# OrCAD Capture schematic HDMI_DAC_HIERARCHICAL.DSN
size A
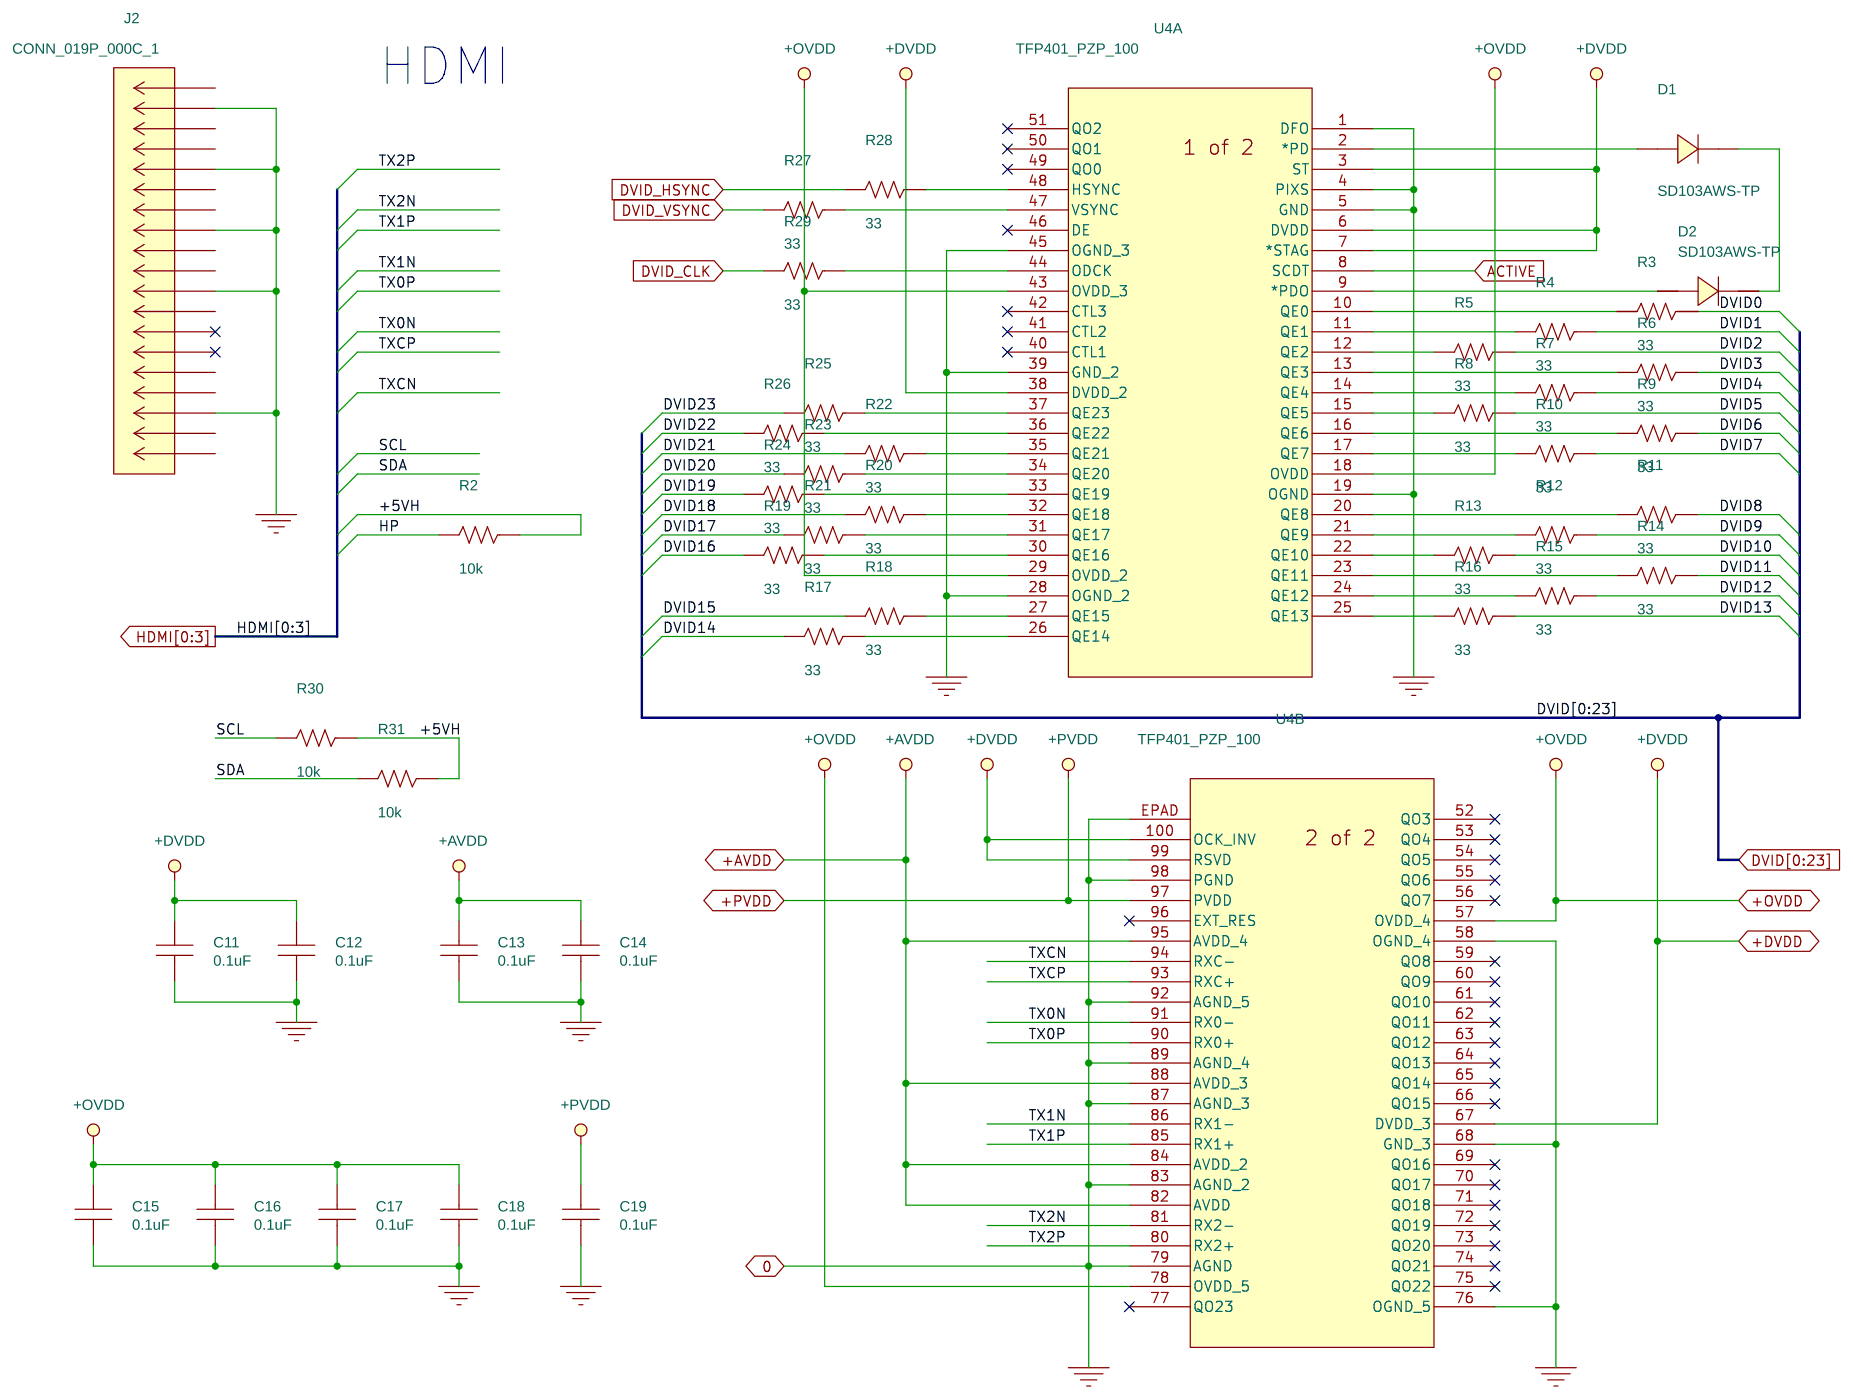
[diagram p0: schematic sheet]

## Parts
C11  0.1uF  [SMC0603]
C12  0.1uF  [SMC0603]
C13  0.1uF  [SMC0603]
C14  0.1uF  [SMC0603]
C15  0.1uF  [SMC0603]
C16  0.1uF  [SMC0603]
C17  0.1uF  [SMC0603]
C18  0.1uF  [SMC0603]
C19  0.1uF  [SMC0603]
D1  SD103AWS-TP  [SMD0805]
D2  SD103AWS-TP  [SMD0805]
J2  CONN_019P_000C_1  [CONN_208658-1051_MOL]
R2  10k  [SMR0603]
R3  33  [SMR0603]
R4  33  [SMR0603]
R5  33  [SMR0603]
R6  33  [SMR0603]
R7  33  [SMR0603]
R8  33  [SMR0603]
R9  33  [SMR0603]
R10  33  [SMR0603]
R11  33  [SMR0603]
R12  33  [SMR0603]
R13  33  [SMR0603]
R14  33  [SMR0603]
R15  33  [SMR0603]
R16  33  [SMR0603]
R17  33  [SMR0603]
R18  33  [SMR0603]
R19  33  [SMR0603]
R20  33  [SMR0603]
R21  33  [SMR0603]
R22  33  [SMR0603]
R23  33  [SMR0603]
R24  33  [SMR0603]
R25  33  [SMR0603]
R26  33  [SMR0603]
R27  33  [SMR0603]
R28  33  [SMR0603]
R29  33  [SMR0603]
R30  10k  [SMR0603]
R31  10k  [SMR0603]
U4  TFP401_PZP_100  [PZP100_5P2X5P2]  (sections A,B)

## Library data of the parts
C11-C19 = CAP_NP
D1 D2 = DIODE_0
J2 = 2086581051
R2-R31 = R
U4 = TFP401PZP

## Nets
+5VH: R2.1 R30.1 R31.1
+AVDD: C13.1 C14.1 U4.82(AVDD) U4.84(AVDD_2) U4.88(AVDD_3) U4.95(AVDD_4)
+DVDD: C11.1 C12.1 U4.3(ST) U4.6(DVDD) U4.7(*STAG) U4.38(DVDD_2) U4.67(DVDD_3) U4.99(RSVD) U4.100(OCK_INV)
+PVDD: C19.1 U4.97(PVDD)
0: C11.2 C12.2 C13.2 C14.2 C15.2 C16.2 C17.2 C18.2 C19.2 J2.2 J2.5 J2.8 J2.11 J2.17 U4.1(DFO) U4.4(PIXS) U4.5(GND) U4.19(OGND) U4.28(OGND_2) U4.39(GND_2) U4.45(OGND_3) U4.58(OGND_4) U4.68(GND_3) U4.76(OGND_5) U4.79(AGND) U4.83(AGND_2) U4.87(AGND_3) U4.89(AGND_4) U4.92(AGND_5) U4.98(PGND) U4.EPAD
+OVDD: C15.1 C16.1 C17.1 C18.1 U4.18(OVDD) U4.29(OVDD_2) U4.43(OVDD_3) U4.57(OVDD_4) U4.78(OVDD_5)
ACTIVE: U4.8(SCDT)
DVID0: R3.1
DVID1: R4.1
DVID2: R5.1
DVID3: R6.1
DVID4: R7.1
DVID5: R8.1
DVID6: R9.1
DVID7: R10.1
DVID8: R11.1
DVID9: R12.1
DVID10: R13.1
DVID11: R14.1
DVID12: R15.1
DVID13: R16.1
DVID14: R17.2
DVID15: R18.2
DVID16: R19.2
DVID17: R21.2
DVID18: R20.2
DVID19: R24.2
DVID20: R23.2
DVID21: R22.2
DVID22: R26.2
DVID23: R25.2
DVID_CLK: R29.2
DVID_HSYNC: R28.2
DVID_VSYNC: R27.2
HP: R2.2
SCL: R30.2
SDA: R31.2
TX0N: U4.91(RX0-)
TX0P: U4.90(RX0+)
TX1N: U4.86(RX1-)
TX1P: U4.85(RX1+)
TX2N: U4.81(RX2-)
TX2P: U4.80(RX2+)
TXCN: U4.94(RXC-)
TXCP: U4.93(RXC+)
N11616: R3.2 U4.10(QE0)
N11680: R4.2 U4.11(QE1)
N11691: R5.2 U4.12(QE2)
N11721: R6.2 U4.13(QE3)
N11753: R7.2 U4.14(QE4)
N11785: R8.2 U4.15(QE5)
N11817: R9.2 U4.16(QE6)
N11849: R10.2 U4.17(QE7)
N12249: R11.2 U4.20(QE8)
N12281: R12.2 U4.21(QE9)
N12313: R13.2 U4.22(QE10)
N12345: R14.2 U4.23(QE11)
N12377: R15.2 U4.24(QE12)
N12409: R16.2 U4.25(QE13)
N12613: R17.1 U4.26(QE14)
N13128: R18.1 U4.27(QE15)
N13531: R19.1 U4.30(QE16)
N13809: R20.1 U4.32(QE18)
N13817: R21.1 U4.31(QE17)
N13972: R22.1 U4.35(QE21)
N14004: R23.1 U4.34(QE20)
N14012: R24.1 U4.33(QE19)
N14149: R25.1 U4.37(QE23)
N14157: R26.1 U4.36(QE22)
N14872: R27.1 U4.47(VSYNC)
N15122: R28.1 U4.48(HSYNC)
N15187: R29.1 U4.44(ODCK)
N15634: D1.A U4.2(*PD)
N15666: D2.A U4.9(*PDO)
N15670: D1.C(K) D2.C(K)

Not connected (* = marked no-connect by the designer): J2 1 3 4 6 7 9 10 12 13* 14* 15 16 18 19; U4 40(CTL1)* 41(CTL2)* 42(CTL3)* 46(DE)* 49(QO0)* 50(QO1)* 51(QO2)* 52(QO3)* 53(QO4)* 54(QO5)* 55(QO6)* 56(QO7)* 59(QO8)* 60(QO9)* 61(QO10)* 62(QO11)* 63(QO12)* 64(QO13)* 65(QO14)* 66(QO15)* 69(QO16)* 70(QO17)* 71(QO18)* 72(QO19)* 73(QO20)* 74(QO21)* 75(QO22)* 77(QO23)* 96(EXT_RES)*

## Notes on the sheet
- HDMI
